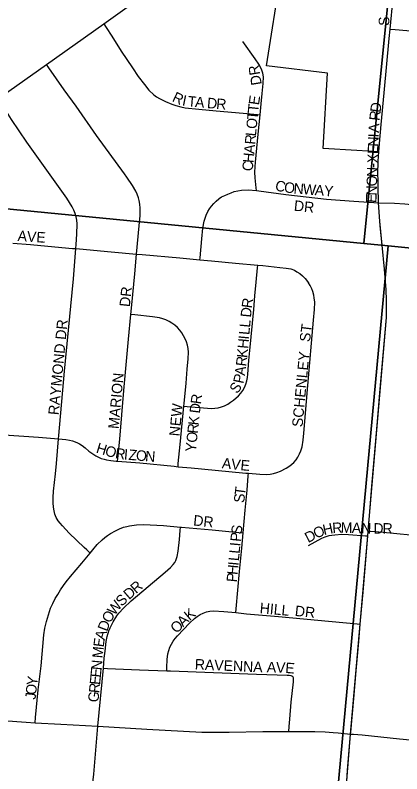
# Model space of a CAD drawing. Extents: x 1410790 to 1770854, y 566777 to 831614.
# Drawn here: x 1563372 to 1565214, y 682819 to 686433 of the extents above; entities that cross this region are included whole.
import ezdxf

# ---------------------------------------------------------------- set-up
doc = ezdxf.new("R2010")
doc.units = 0
for name, color, linetype in [('GM_X_City_Street', 7, 'Continuous'), ('GM_X_City_Street_Text', 7, 'Continuous'), ('GM_X_Corporation', 7, 'Continuous'), ('GM_X_County_Road', 7, 'Continuous'), ('GM_X_Section', 7, 'Continuous'), ('GM_X_Township_Subdivision', 7, 'Continuous'), ('GM_X_Township_Subdivision_Text', 7, 'Continuous')]:
    doc.layers.add(name, color=color, linetype=linetype)

msp = doc.modelspace()

# ---------------------------------------------------------------- linework, layer by layer
at = {"layer": 'GM_X_City_Street'}
for points in [[(1565158.6, 686366.6), (1565173.4, 686518), (1565177.4, 686566.1)], [(1565103.7, 685539.7), (1565103, 685549.6), (1565101.1, 685606.3), (1565100.7, 685647.3), (1565100.4, 685675.7), (1565101.8, 685737.3), (1565104.6, 685782.8), (1565107.4, 685821.3), (1565115.4, 685912.5), (1565129.8, 686063.7), (1565154.3, 686321.6), (1565158.6, 686366.6)], [(1565158.6, 686366.6), (1565182.5, 686364.6), (1565312.7, 686353.4), (1565581.9, 686328.2)], [(1565103.7, 685539.7), (1565179.1, 685537.6), (1565229, 685534.6), (1565277.9, 685530.4), (1565302.4, 685526.7), (1565327.1, 685521.5), (1565373.4, 685506.4), (1565404.2, 685495.1), (1565432.6, 685480.7), (1565469, 685460)], [(1565111.6, 685429), (1565109.5, 685451.6), (1565103.7, 685539.7)], [(1565053.8, 683975.3), (1565065.4, 683974.4), (1565125.6, 683969.8), (1565255.8, 683957.8), (1565451, 683940), (1565508.5, 683934.2)], [(1564970.2, 683008.4), (1564983.3, 683007.5), (1565024.5, 683004.4), (1565203.5, 682985.7), (1565420, 682964.3)]]:
    msp.add_lwpolyline(points, dxfattribs=at)
at = {"layer": 'GM_X_Corporation'}
msp.add_lwpolyline([(1564948.7, 682746.4), (1564970.2, 683008.4), (1565016.3, 683532.1), (1565051.8, 683952.6), (1565053.8, 683975.3), (1565140.4, 684993.2), (1565141.1, 685075.4), (1565139.9, 685124.9), (1565132.1, 685223.1), (1565120.2, 685337.4), (1565109.5, 685451.6), (1565103.7, 685539.7), (1565103, 685549.6), (1565101.1, 685606.3), (1565100.7, 685647.2), (1565100.4, 685675.7), (1565101.8, 685737.3), (1565104.6, 685782.8), (1565000.3, 685787.8), (1564839.3, 685797.6), (1564860.1, 686157.1), (1564570.2, 686191.3), (1564638.3, 686625.4)], dxfattribs=at)
at = {"layer": 'GM_X_County_Road'}
for points in [[(1563793.7, 686392.2), (1563927.8, 686487.4), (1564095.8, 686605.4)], [(1563520.9, 686198.6), (1563793.7, 686392.2)], [(1563291.5, 686035.9), (1563379.9, 686098.6), (1563520.9, 686198.6)], [(1565053.8, 683975.3), (1565058.1, 684028.3), (1565073.1, 684208), (1565089.5, 684387.8), (1565102, 684535), (1565109.5, 684633.2), (1565125.6, 684813), (1565140.4, 684993.2), (1565141.1, 685075.4), (1565139.8, 685124.9), (1565132.1, 685223.1), (1565120.2, 685337.4), (1565111.6, 685429)], [(1565016.3, 683532.1), (1565029.3, 683684.8), (1565051.8, 683952.6)], [(1565051.8, 683952.6), (1565053.8, 683975.3)], [(1564970.2, 683008.4), (1564970.8, 683016.4), (1564985.5, 683177.5), (1564997.1, 683308.9), (1565009.3, 683449.3), (1565016.3, 683532.1)], [(1564948.7, 682746.4), (1564949.8, 682758.7), (1564956.1, 682836.5), (1564970.2, 683008.4)]]:
    msp.add_lwpolyline(points, dxfattribs=at)
at = {"layer": 'GM_X_Section'}
for points in [[(1560235.6, 691235.5), (1565558.1, 690607), (1565032.7, 685345.6), (1559844.1, 685849.6), (1559732.3, 685861.3)], [(1565558.1, 690607), (1570902.9, 690112), (1570366.9, 684817.2), (1565148.5, 685333.7), (1565032.7, 685345.6)], [(1559844.1, 685849.6), (1565032.7, 685345.6), (1565148.5, 685333.7), (1564673.5, 680210.6), (1559303.8, 680639.6)], [(1570366.9, 684817.2), (1570438.7, 684810.1), (1569973.9, 679696.7), (1564673.5, 680210.6), (1565148.5, 685333.7)]]:
    msp.add_lwpolyline(points, close=True, dxfattribs=at)
at = {"layer": 'GM_X_Township_Subdivision'}
for points in [[(1563793.7, 686392.2), (1563805.2, 686374.7), (1563832.5, 686333.1), (1563877.6, 686262.3), (1563930.4, 686181.9), (1563958.4, 686141.6), (1563987.5, 686102.6), (1564008.7, 686076.2), (1564033, 686054.4), (1564045.6, 686044.9), (1564059.9, 686035.8), (1564088.1, 686021.9), (1564119, 686009.3), (1564137.6, 686002.4), (1564161.1, 685996.3), (1564182.3, 685992.4), (1564247.4, 685985), (1564329.9, 685976.7), (1564458.8, 685966.3), (1564527, 685960.2), (1564538.8, 685959.2)], [(1564538.8, 685959.2), (1564543.9, 686010.8), (1564548.2, 686059.7), (1564553, 686107), (1564554.8, 686139.5), (1564552.6, 686156.4), (1564547.8, 686171.2), (1564541.3, 686185.1), (1564532.6, 686200.3), (1564515.3, 686225), (1564456.7, 686308.3)], [(1563950.5, 685294.5), (1563963.1, 685429.9), (1563966.9, 685479.6), (1563966.9, 685513.5), (1563965.6, 685533), (1563963.4, 685550.8), (1563960, 685563.4), (1563953.4, 685580.7), (1563947.4, 685594.2), (1563931.3, 685621.8), (1563904, 685661.9), (1563893.1, 685676.6), (1563759.9, 685860.7), (1563662.2, 685999.1), (1563605.8, 686077.7), (1563532, 686182.7), (1563520.9, 686198.6)], [(1563661.7, 685320.9), (1563663.3, 685340.7), (1563666.4, 685390), (1563667.4, 685439.5), (1563666, 685456.3), (1563662.9, 685472.9), (1563658.1, 685489), (1563651.8, 685504.7), (1563644.2, 685519.6), (1563618, 685561.6), (1563427.4, 685828), (1563354.4, 685936.5), (1563306.4, 686012.3), (1563291.5, 686035.9)], [(1564521.3, 685597.8), (1564520, 685610), (1564514.8, 685658.6), (1564514, 685685.9), (1564514.8, 685710.2), (1564516.6, 685733.2), (1564529.6, 685866.5), (1564538.8, 685959.2)], [(1564344.4, 685559.5), (1564355.8, 685567.1), (1564370.4, 685574.6), (1564385.4, 685581.2), (1564400.7, 685586.9), (1564416.1, 685592.7), (1564433, 685597.1), (1564450, 685599.2), (1564482.9, 685600.5), (1564521.3, 685597.8)], [(1564521.3, 685597.8), (1564532.9, 685597.1), (1564660.9, 685578.8), (1564855.1, 685557.4), (1564985.6, 685547.6), (1565032.9, 685544.5), (1565081.4, 685541.2), (1565103.7, 685539.7)], [(1564252.1, 685267.5), (1564252.9, 685277.6), (1564260.7, 685368.3), (1564265.9, 685417.8), (1564272.4, 685451.6), (1564282, 685480.7), (1564289.8, 685497.6), (1564297.2, 685509.8), (1564307.2, 685522.8), (1564318.2, 685535.8), (1564329.6, 685547.5), (1564342.2, 685558.1), (1564344.4, 685559.5)], [(1563361.5, 685347.2), (1563444.8, 685340.3), (1563560.8, 685329.4), (1563645.8, 685322.1), (1563661.7, 685320.9)], [(1563579.1, 684415.2), (1563580.3, 684429.9), (1563606.7, 684737.7), (1563619.8, 684868), (1563650.3, 685177.6), (1563661.7, 685320.9)], [(1563661.7, 685320.9), (1563679.2, 685319.9), (1563829, 685306.4), (1563950.5, 685294.5)], [(1563923.5, 685007.5), (1563927.6, 685053), (1563941.7, 685200.5), (1563950.5, 685294.5)], [(1563950.5, 685294.5), (1563977.7, 685292.4), (1564157.1, 685276.5), (1564252.1, 685267.5)], [(1564252.1, 685267.5), (1564306.7, 685262.4), (1564421.7, 685251.5), (1564527.7, 685242.5)], [(1564176.3, 684569.8), (1564191.5, 684568.7), (1564306.7, 684559.8), (1564323, 684560.3), (1564339.2, 684562.5), (1564354.9, 684566.6), (1564370.1, 684572.6), (1564384.6, 684580), (1564398.5, 684588.7), (1564411.6, 684598.3), (1564436, 684620.1), (1564446.9, 684632.2), (1564456.3, 684645.4), (1564463.9, 684659.9), (1564470.2, 684674.9), (1564475, 684690.5), (1564478.3, 684706.5), (1564480.2, 684722.7), (1564485.5, 684787.7), (1564490.2, 684836.3), (1564508.7, 685031.3), (1564514.2, 685096), (1564520.9, 685160.9), (1564526.5, 685228.8), (1564527.7, 685242.5)], [(1564527.7, 685242.5), (1564551.2, 685240.5), (1564633.6, 685231.8), (1564663.6, 685228.3), (1564685.3, 685224), (1564702.2, 685217.9), (1564714.4, 685211), (1564728.3, 685201.8), (1564741.7, 685191), (1564753.4, 685178.4), (1564769.5, 685157.6)], [(1564681.4, 684286.9), (1564700.1, 684302.5), (1564710.5, 684315.1), (1564719.1, 684328.1), (1564727, 684343.8), (1564733.1, 684358.1), (1564738.7, 684375.9), (1564743.5, 684408.4), (1564746.9, 684441), (1564766, 684668.8), (1564793.8, 684980.5), (1564798.1, 685030.9), (1564799.9, 685065.6), (1564797.3, 685086.4), (1564795.1, 685099.8), (1564789.9, 685116.8), (1564785.6, 685129.4), (1564777.7, 685145), (1564769.5, 685157.6)], [(1563859.6, 684308.6), (1563861, 684321.6), (1563871, 684413.2), (1563890.5, 684645), (1563912.7, 684889.1), (1563923.5, 685007.5)], [(1564176.3, 684569.8), (1564177.6, 684582.7), (1564186.8, 684679.5), (1564192, 684746.8), (1564196.3, 684795.8), (1564197.2, 684828), (1564196.1, 684844.4), (1564193.3, 684860.5), (1564188.3, 684876.2), (1564181.6, 684891.1), (1564165.4, 684919.7), (1564155.8, 684933), (1564144.8, 684945.2), (1564132.4, 684955.9), (1564119.1, 684965.6), (1564105.1, 684974.1), (1564090.3, 684981.3), (1564075, 684987), (1564059.2, 684991.5), (1564026.6, 684996.8), (1563942.8, 685005.5), (1563923.5, 685007.5)], [(1564148, 684282.1), (1564149, 684297.1), (1564157.7, 684387.4), (1564176.3, 684569.8)], [(1563207.4, 684445.3), (1563319.4, 684434.5), (1563482.7, 684422), (1563579.1, 684415.2)], [(1563729.1, 683870.2), (1563712.7, 683886.2), (1563700.8, 683897.6), (1563629.9, 683965.4), (1563596.9, 684000.1), (1563585.9, 684012.8), (1563576.8, 684024.5), (1563568.1, 684040.5), (1563561.6, 684056.6), (1563557.7, 684072.2), (1563554.7, 684089.6), (1563553.8, 684110), (1563553.8, 684135.6), (1563555.1, 684166), (1563563.9, 684248.5), (1563569.5, 684297.1), (1563579.1, 684415.2)], [(1563579.1, 684415.2), (1563613.2, 684411.2), (1563630.5, 684408), (1563644.7, 684404.9), (1563658.1, 684400.5), (1563668.7, 684395.6), (1563678.4, 684390.6), (1563691.2, 684382.4), (1563705.1, 684372.2), (1563723.7, 684356.6), (1563741.3, 684342.8), (1563756.5, 684333.8), (1563771.7, 684326.4), (1563782.4, 684321.7), (1563796.3, 684317.3), (1563806.9, 684314.8), (1563827.7, 684311.9), (1563853.3, 684309), (1563859.6, 684308.6)], [(1563859.6, 684308.6), (1563966.4, 684300.3), (1564129.7, 684283.9), (1564148, 684282.1)], [(1564148, 684282.1), (1564210.5, 684276.5), (1564325.3, 684265.9), (1564471.3, 684251.7), (1564483.9, 684250.8)], [(1564483.9, 684250.8), (1564537.7, 684246.6), (1564570.3, 684245.3), (1564587.7, 684247), (1564603.3, 684249.6), (1564618.8, 684254.4), (1564635.4, 684260), (1564663.4, 684274.9), (1564681.4, 684286.9)], [(1564457.9, 683967), (1564468.6, 684074.5), (1564477.4, 684169.7), (1564482.9, 684238.5), (1564483.9, 684250.8)], [(1563729.1, 683870.2), (1563742, 683885.7), (1563763.3, 683910.6), (1563786.1, 683934.2), (1563798.5, 683944.9), (1563811.8, 683954.5), (1563825.7, 683963.1), (1563849.3, 683975.8), (1563868.8, 683985.3), (1563887.9, 683993.2), (1563904.5, 683997.4), (1563917, 684000.5), (1563949.5, 684005.3), (1563983.8, 684007.1), (1564015.1, 684005.8), (1564079.4, 684001.2), (1564160.1, 683994.3)], [(1563792.2, 683321.7), (1563796.8, 683369.9), (1563800.4, 683402.5), (1563806.3, 683448.7), (1563810.4, 683472.4), (1563817.9, 683499.3), (1563824, 683514.4), (1563839.1, 683543.6), (1563856.6, 683571.3), (1563866.6, 683584.3), (1563888.5, 683608.6), (1563924.3, 683642.3), (1564087.3, 683779.6), (1564111.8, 683801.5), (1564125.5, 683815.4), (1564132.7, 683824.8), (1564138, 683834.9), (1564143.9, 683854.4), (1564148.7, 683879.9), (1564155.2, 683934.4), (1564158.7, 683977.7), (1564160.1, 683994.3)], [(1564160.1, 683994.3), (1564162.7, 683994), (1564163.8, 683993.9), (1564310.7, 683980.6), (1564437.8, 683968.9), (1564457.9, 683967)], [(1564423.1, 683586.7), (1564424.8, 683604.8), (1564440.8, 683781.9), (1564451.2, 683894.3), (1564457.9, 683967)], [(1564769.8, 683907.3), (1564833.2, 683940.8), (1564848.3, 683947.3), (1564858.7, 683951), (1564868.3, 683953.8), (1564880.2, 683955.9), (1564894.3, 683958.1), (1564929.1, 683960.3), (1564959.9, 683959), (1565041.1, 683953.4), (1565051.8, 683952.6)], [(1563467.1, 683062.4), (1563469.5, 683086.5), (1563482.4, 683219.5), (1563495.6, 683333.5), (1563508.6, 683480.5), (1563513.3, 683512.9), (1563520.8, 683544.8), (1563530.7, 683576.1), (1563541.1, 683607.3), (1563551.1, 683629.7), (1563562.8, 683654.6), (1563574.7, 683673.2), (1563588, 683695), (1563602.5, 683715.7), (1563614.9, 683734.1), (1563634.9, 683759.2), (1563689.8, 683822.6), (1563729.1, 683870.2)], [(1564094.1, 683309.8), (1564094.8, 683325), (1564096.5, 683364.1), (1564099.6, 683390.7), (1564103.7, 683406.6), (1564109.3, 683422.1), (1564116.4, 683436.9), (1564125, 683450.9), (1564134.8, 683464.1), (1564145.6, 683476.5), (1564202.7, 683535.8), (1564226.7, 683558.3), (1564239.7, 683568.4), (1564253.5, 683577.3), (1564268.2, 683584.8), (1564283.7, 683590.3), (1564299.8, 683593.8), (1564316.2, 683595.2), (1564365.5, 683592.6), (1564423.1, 683586.7)], [(1564423.1, 683586.7), (1564473.6, 683581.5), (1564626.2, 683567.7), (1565002.2, 683533.3), (1565016.3, 683532.1)], [(1563765.8, 683045.3), (1563792.2, 683321.7)], [(1563792.2, 683321.7), (1563811.8, 683320.8), (1563965, 683314.3), (1564094.1, 683309.8)], [(1564094.1, 683309.8), (1564112.5, 683309.1), (1564521.4, 683294.2), (1564619.5, 683290.9), (1564667.2, 683289.2), (1564677.2, 683288.7), (1564685, 683287.8), (1564690.2, 683286.1), (1564694.6, 683282.6)], [(1564676.2, 683019.9), (1564678.1, 683044.3), (1564680.7, 683078.6), (1564687.2, 683159.4), (1564697.6, 683256.6), (1564698.6, 683266.5), (1564697.6, 683276.6), (1564694.6, 683282.6)], [(1563293.4, 683074.2), (1563315.3, 683072.1), (1563425, 683064.8), (1563467.1, 683062.4)], [(1563467.1, 683062.4), (1563589.1, 683055.3), (1563765.8, 683045.3)], [(1563732.7, 682698), (1563734, 682707.1), (1563747, 682816.6), (1563765.8, 683045.3)], [(1563765.8, 683045.3), (1563999.5, 683032.1), (1564260.7, 683017.8), (1564320.9, 683016.8), (1564392.3, 683017.8), (1564551.4, 683019.8), (1564673.8, 683019.8), (1564676.2, 683019.9)], [(1564676.2, 683019.9), (1564800.3, 683020.9), (1564848.2, 683018.8), (1564886.5, 683015.3), (1564911.4, 683013.5), (1564970.2, 683008.4)]]:
    msp.add_lwpolyline(points, dxfattribs=at)

# ---------------------------------------------------------------- texts
at = {"layer": 'GM_X_City_Street_Text'}
for s, rotation, p in [('S', 90, (1565154.4, 686382.4)), ('D', 83.165, (1565112.7, 685967.5)), ('R', 83.3554, (1565108.1, 685928.2)), ('A', 87.0263, (1565104.7, 685872)), ('I', 87.9452, (1565103.9, 685850.2)), ('N', 87.9671, (1565102.3, 685806.2)), ('E', 87.983, (1565101.1, 685771)), ('X', 87.9452, (1565099.5, 685727)), ('-', 87.9936, (1565098.8, 685705.1)), ('N', 87.9452, (1565097.2, 685661)), ('O', 87.9671, (1565095.6, 685617.1)), ('N', 87.9718, (1565094.1, 685573.1)), ('E', 87.9507, (1565092.8, 685537.9))]:
    msp.add_text(s, height=50, rotation=rotation, dxfattribs=at).set_placement(p)
at = {"layer": 'GM_X_Township_Subdivision_Text'}
for s, rotation, p in [('DR', 99.4574, (1564547.3, 686103.6)), ('R', 334.8364, (1564116.4, 686024.9)), ('I', 348.8454, (1564164.9, 686003.9)), ('T', 355.0373, (1564192.3, 685998.8)), ('A', 355.139, (1564227.5, 685995.8)), ('E', 81.6091, (1564533.3, 686002.7)), ('D', 355.139, (1564284.5, 685990.9)), ('R', 355.1254, (1564328.3, 685987.2)), ('T', 84.2527, (1564529.8, 685968.3)), ('T', 84.5733, (1564526.5, 685933.4)), ('O', 84.5711, (1564522.4, 685889.5)), ('R', 84.5758, (1564515.3, 685815.1)), ('L', 84.5733, (1564519, 685854.5)), ('A', 84.5863, (1564511.1, 685771.3)), ('H', 84.5711, (1564507, 685727.5)), ('C', 84.5758, (1564503.2, 685688.1)), ('C', 347.2894, (1564607.2, 685599.5)), ('O', 352.5017, (1564650.7, 685590)), ('N', 355.4602, (1564697.1, 685583.9)), ('W', 355.5208, (1564741, 685580.4)), ('A', 355.5141, (1564798.1, 685576)), ('Y', 355.5141, (1564841.9, 685572.5)), ('DR', 353.9889, (1564698.3, 685501.9)), ('AVE', 356.0531, (1563382.5, 685357.8)), ('DR', 83.994, (1563918.1, 685041.4)), ('R', 81.8373, (1564499.6, 685034.8)), ('D', 84.1763, (1564495.2, 684991.5)), ('RAYMOND DR', 84.5877, (1563579.2, 684526.4)), ('L', 84.7574, (1564490.8, 684943.4)), ('ST', 82.8792, (1564776.1, 684874.3)), ('L', 84.7746, (1564487.6, 684908.4)), ('H', 84.7615, (1564481.6, 684842.6)), ('I', 84.8159, (1564485.6, 684886.5)), ('K', 84.5863, (1564477.4, 684798.7)), ('SCHENLEY', 84.595, (1564740.8, 684469.1)), ('R', 83.2015, (1564472.6, 684758)), ('A', 82.4457, (1564466.7, 684713.7)), ('MARION', 84.8967, (1563865.2, 684460.4)), ('P', 78.1397, (1564458.8, 684675.2)), ('S', 54.8323, (1564429.7, 684626.2)), ('R', 82.1807, (1564256.9, 684577.5)), ('NEW', 84.647, (1564155.7, 684425.3)), ('D', 83.2084, (1564251.8, 684534)), ('K', 83.8468, (1564245.6, 684477.3)), ('R', 84.0393, (1564241.5, 684438)), ('O', 84.0448, (1564236.9, 684394.2)), ('H', 343.2484, (1563754.2, 684349.8)), ('O', 343.4783, (1563796.5, 684337)), ('Y', 84.0665, (1564232.4, 684350.4)), ('R', 351.361, (1563846, 684322.9)), ('I', 355.2066, (1563888.8, 684316.5)), ('Z', 355.3418, (1563910.9, 684314.7)), ('O', 355.336, (1563946, 684311.8)), ('N', 355.3289, (1563989.8, 684308.2)), ('A', 353.7262, (1564355.3, 684275.3)), ('V', 353.7401, (1564399, 684270.5)), ('E', 354.669, (1564443.6, 684265.6)), ('T', 82.631, (1564466.5, 684142.6)), ('S', 85.2409, (1564463.6, 684108.1)), ('DR', 353.9946, (1564218.8, 684002.5)), ('S', 82.2717, (1564449.8, 683957.3)), ('O', 26.0469, (1564806.6, 683937.7)), ('H', 12.1803, (1564843.1, 683955.9)), ('R', 3.4021, (1564884.1, 683964.9)), ('M', 359.0801, (1564922.7, 683967.3)), ('A', 357.3439, (1564975.1, 683966.4)), ('N', 358.2983, (1565019.9, 683964.4)), ('D', 359.9703, (1565078.7, 683963)), ('R', 359.9941, (1565122.7, 683963)), ('P', 84.6102, (1564446.6, 683922.8)), ('D', 26.956, (1564767.6, 683917.8)), ('I', 84.6502, (1564444.5, 683900.9)), ('L', 84.6102, (1564441.2, 683865.9)), ('L', 84.6371, (1564437.9, 683830.8)), ('H', 84.6156, (1564431.7, 683765.1)), ('I', 84.6156, (1564435.8, 683808.9)), ('P', 84.6374, (1564428.4, 683730)), ('R', 40.9095, (1563947.8, 683674.8)), ('D', 40.9166, (1563914.5, 683646)), ('S', 42.7974, (1563879.2, 683613.6)), ('W', 51.8758, (1563845.3, 683570.1)), ('HILL', 354.6433, (1564535.5, 683584.5)), ('DR', 353.9946, (1564702.8, 683571.3)), ('O', 60.3934, (1563824.6, 683533.5)), ('K', 39.7776, (1564202.7, 683545.8)), ('D', 69.2457, (1563809.9, 683494.2)), ('A', 44.405, (1564172.1, 683515.7)), ('O', 44.405, (1564140.7, 683484.9)), ('A', 73.352, (1563797.6, 683453)), ('E', 82.6852, (1563793.6, 683420.2)), ('M', 84.5157, (1563788.6, 683368)), ('N', 84.5189, (1563783.1, 683311.1)), ('RAVENNA', 357.4752, (1564227, 683316.2)), ('A', 357.6386, (1564570.1, 683303)), ('V', 357.6277, (1564614.1, 683301.2)), ('E', 355.6788, (1564657.6, 683299.4)), ('E', 84.5273, (1563779.8, 683276.1)), ('Y', 82.4602, (1563475.9, 683236.3)), ('E', 84.524, (1563776.4, 683241)), ('O', 83.8468, (1563471.2, 683192.9)), ('R', 84.5113, (1563772.6, 683201.6)), ('J', 84.7027, (1563469.2, 683171.2)), ('G', 84.5275, (1563768.4, 683157.8))]:
    msp.add_text(s, height=50, rotation=rotation, dxfattribs=at).set_placement(p)

doc.saveas('drawing.dxf')
